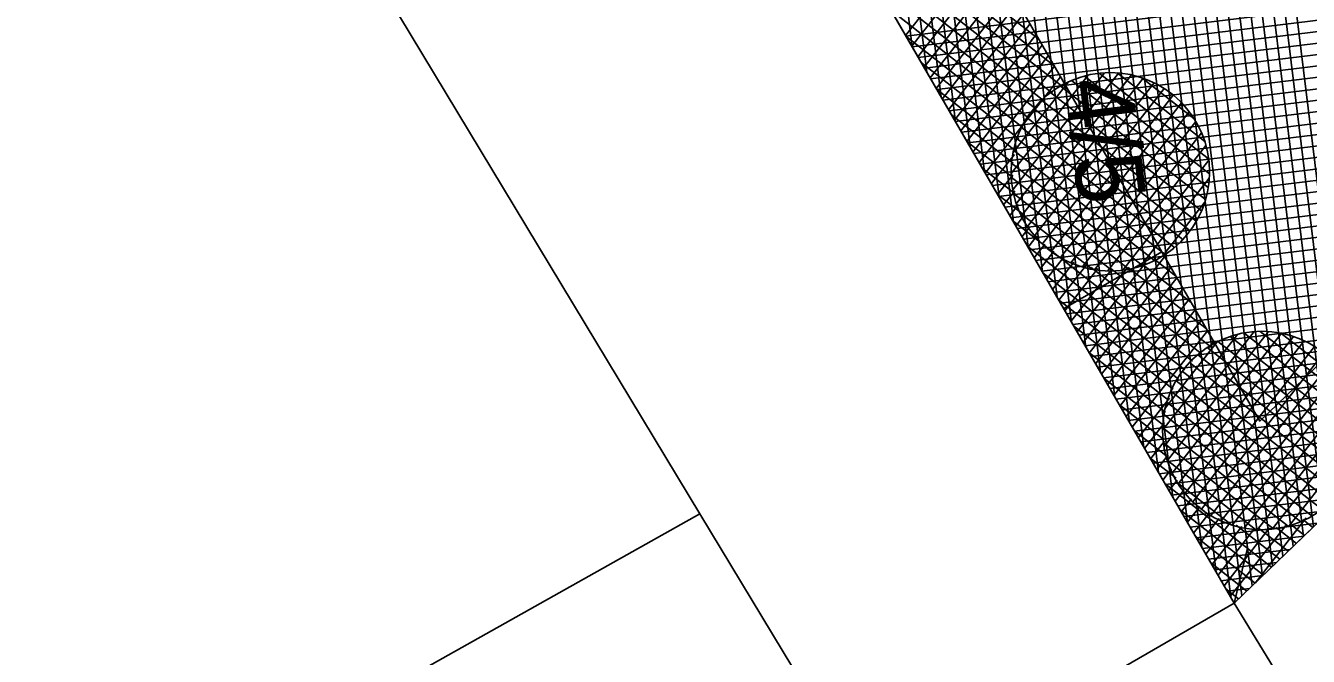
# Model space of a CAD drawing. Extents: x -566982 to -566809, y -1095912 to -1095685.
# Drawn here: x -566913.58 to -566890.96, y -1095828.46 to -1095817.35 of the extents above; entities that cross this region are included whole.
import ezdxf

# ---------------------------------------------------------------- set-up
doc = ezdxf.new("R2010")
doc.units = 0
for name, color, linetype in [('Vrstva 1', 7, 'Continuous'), ('Vrstva 26', 7, 'Continuous'), ('Vrstva 4', 7, 'Continuous'), ('Vrstva 40', 7, 'Continuous'), ('Vrstva 41', 7, 'Continuous'), ('Vrstva 42', 7, 'Continuous'), ('Vrstva 43', 7, 'Continuous'), ('Vrstva 44', 7, 'Continuous')]:
    doc.layers.add(name, color=color, linetype=linetype)

msp = doc.modelspace()

# ---------------------------------------------------------------- linework, layer by layer
at = {"layer": 'Vrstva 1'}
for p, q in [((-566956.66, -1095716.28), (-566892.27, -1095827.53)), ((-566928.71, -1095781.18), (-566901.69, -1095825.95)), ((-566880.71, -1095816.4), (-566892.27, -1095827.53)), ((-566901.69, -1095825.95), (-566898.55, -1095831.15)), ((-566898.55, -1095831.15), (-566892.27, -1095827.53)), ((-566892.27, -1095827.53), (-566889.61, -1095831.87))]:
    msp.add_line(p, q, dxfattribs=at)
at = {"layer": 'Vrstva 26'}
msp.add_line((-566892.034, -1095826.558), (-566892.27, -1095827.53), dxfattribs=at)
at = {"layer": 'Vrstva 4'}
msp.add_line((-566906.65, -1095828.74), (-566901.69, -1095825.95), dxfattribs=at)
at = {"layer": 'Vrstva 41'}
for p, q in [((-566899.133, -1095815.673), (-566895.47, -1095818.539)), ((-566898.864, -1095816.137), (-566895.629, -1095818.669)), ((-566896.416, -1095816.394), (-566897.738, -1095818.083)), ((-566898.595, -1095816.602), (-566895.766, -1095818.815)), ((-566897.348, -1095816.611), (-566898.062, -1095817.523)), ((-566897.091, -1095816.607), (-566897.954, -1095817.71)), ((-566896.793, -1095816.551), (-566897.846, -1095817.896)), ((-566897.663, -1095816.57), (-566895.292, -1095818.425)), ((-566896.301, -1095816.572), (-566897.63, -1095818.269)), ((-566897.286, -1095816.61), (-566895.446, -1095818.05)), ((-566896.983, -1095816.594), (-566895.714, -1095817.586)), ((-566896.194, -1095816.758), (-566897.522, -1095818.456)), ((-566898.327, -1095817.066), (-566895.886, -1095818.976)), ((-566896.086, -1095816.945), (-566897.414, -1095818.642)), ((-566895.978, -1095817.131), (-566897.306, -1095818.829)), ((-566895.87, -1095817.318), (-566897.198, -1095819.016)), ((-566898.058, -1095817.53), (-566895.987, -1095819.15)), ((-566895.762, -1095817.504), (-566897.09, -1095819.202)), ((-566895.654, -1095817.691), (-566896.982, -1095819.389)), ((-566897.789, -1095817.994), (-566896.068, -1095819.341)), ((-566895.546, -1095817.878), (-566896.874, -1095819.575)), ((-566895.438, -1095818.064), (-566896.766, -1095819.762)), ((-566895.33, -1095818.251), (-566896.658, -1095819.948)), ((-566897.521, -1095818.458), (-566896.129, -1095819.547)), ((-566897.252, -1095818.922), (-566896.166, -1095819.772)), ((-566896.983, -1095819.387), (-566896.168, -1095820.025)), ((-566896.144, -1095819.616), (-566896.55, -1095820.135)), ((-566896.715, -1095819.851), (-566896.129, -1095820.309)), ((-566896.171, -1095819.975), (-566896.442, -1095820.321)), ((-566896.138, -1095820.257), (-566896.334, -1095820.508)), ((-566896.446, -1095820.315), (-566896.008, -1095820.658)), ((-566896.073, -1095820.499), (-566896.226, -1095820.695)), ((-566895.982, -1095820.707), (-566896.118, -1095820.881)), ((-566896.177, -1095820.779), (-566893.003, -1095823.263)), ((-566895.872, -1095820.891), (-566896.01, -1095821.068)), ((-566895.746, -1095821.055), (-566895.902, -1095821.254)), ((-566895.605, -1095821.199), (-566895.794, -1095821.441)), ((-566895.909, -1095821.243), (-566893.136, -1095823.413)), ((-566895.449, -1095821.325), (-566895.686, -1095821.627)), ((-566893.494, -1095821.422), (-566894.823, -1095823.12)), ((-566895.28, -1095821.432), (-566895.578, -1095821.814)), ((-566895.093, -1095821.519), (-566895.47, -1095822)), ((-566894.891, -1095821.585), (-566895.362, -1095822.187)), ((-566894.671, -1095821.628), (-566895.254, -1095822.374)), ((-566894.422, -1095821.634), (-566895.146, -1095822.56)), ((-566894.153, -1095821.615), (-566895.039, -1095822.747)), ((-566893.828, -1095821.524), (-566894.931, -1095822.933)), ((-566894.791, -1095821.61), (-566892.851, -1095823.128)), ((-566893.386, -1095821.609), (-566894.715, -1095823.306)), ((-566894.435, -1095821.634), (-566892.68, -1095823.007)), ((-566894.139, -1095821.612), (-566892.759, -1095822.692)), ((-566893.893, -1095821.551), (-566893.028, -1095822.228)), ((-566893.684, -1095821.46), (-566893.297, -1095821.763)), ((-566895.64, -1095821.707), (-566893.251, -1095823.577)), ((-566893.278, -1095821.795), (-566894.607, -1095823.493)), ((-566893.17, -1095821.982), (-566894.499, -1095823.679)), ((-566895.371, -1095822.172), (-566893.347, -1095823.756)), ((-566893.062, -1095822.168), (-566894.391, -1095823.866)), ((-566892.954, -1095822.355), (-566894.283, -1095824.053)), ((-566892.846, -1095822.541), (-566894.175, -1095824.239)), ((-566895.103, -1095822.636), (-566893.424, -1095823.949)), ((-566892.738, -1095822.728), (-566894.067, -1095824.426)), ((-566892.63, -1095822.914), (-566892.728, -1095823.039)), ((-566894.834, -1095823.1), (-566893.479, -1095824.16)), ((-566894.565, -1095823.564), (-566893.506, -1095824.393)), ((-566893.41, -1095823.911), (-566893.959, -1095824.612)), ((-566894.297, -1095824.028), (-566893.501, -1095824.651)), ((-566893.505, -1095824.357), (-566893.851, -1095824.799)), ((-566894.028, -1095824.492), (-566893.444, -1095824.949)), ((-566893.499, -1095824.674), (-566893.743, -1095824.985)), ((-566893.759, -1095824.957), (-566893.291, -1095825.323)), ((-566893.449, -1095824.934), (-566893.635, -1095825.172)), ((-566893.371, -1095825.159), (-566893.527, -1095825.358)), ((-566893.491, -1095825.421), (-566891.609, -1095826.893)), ((-566893.273, -1095825.358), (-566893.419, -1095825.545)), ((-566893.155, -1095825.533), (-566893.311, -1095825.732)), ((-566893.022, -1095825.687), (-566893.203, -1095825.918)), ((-566893.222, -1095825.885), (-566891.754, -1095827.033)), ((-566892.874, -1095825.822), (-566893.095, -1095826.105)), ((-566892.712, -1095825.939), (-566892.987, -1095826.291)), ((-566892.535, -1095826.038), (-566892.879, -1095826.478)), ((-566892.343, -1095826.117), (-566892.771, -1095826.664)), ((-566892.134, -1095826.175), (-566892.663, -1095826.851)), ((-566891.36, -1095826.16), (-566892.339, -1095827.411)), ((-566892.233, -1095826.151), (-566891.463, -1095826.753)), ((-566891.002, -1095826.026), (-566891.9, -1095827.173)), ((-566891.278, -1095826.137), (-566891.027, -1095826.333)), ((-566891.058, -1095826.055), (-566890.881, -1095826.193)), ((-566892.954, -1095826.349), (-566891.9, -1095827.174)), ((-566891.905, -1095826.207), (-566892.555, -1095827.037)), ((-566891.648, -1095826.202), (-566892.447, -1095827.224)), ((-566891.839, -1095826.205), (-566891.318, -1095826.613)), ((-566891.53, -1095826.193), (-566891.172, -1095826.473)), ((-566892.685, -1095826.813), (-566892.045, -1095827.314)), ((-566892.416, -1095827.277), (-566892.191, -1095827.454))]:
    msp.add_line(p, q, dxfattribs=at)
at = {"layer": 'Vrstva 42'}
msp.add_line((-566895.276, -1095822.337), (-566893.544, -1095821.335), dxfattribs=at)
msp.add_lwpolyline([(-566834.15, -1095760.69), (-566836.072, -1095760.136), (-566841.286, -1095779.189), (-566855.268, -1095796.126), (-566881.984, -1095814.851), (-566891.818, -1095824.318), (-566954.342, -1095716.292), (-566956.66, -1095716.28), (-566892.27, -1095827.53), (-566880.71, -1095816.4), (-566853.9, -1095797.61), (-566839.47, -1095780.13)], close=True, dxfattribs=at)
at = {"layer": 'Vrstva 43'}
for p, q in [((-566901.033, -1095792.426), (-566897.945, -1095817.724)), ((-566900.777, -1095792.867), (-566897.69, -1095818.165)), ((-566900.522, -1095793.308), (-566897.435, -1095818.607)), ((-566900.267, -1095793.749), (-566897.179, -1095819.048)), ((-566900.011, -1095794.19), (-566896.924, -1095819.489)), ((-566899.756, -1095794.631), (-566896.669, -1095819.93)), ((-566899.501, -1095795.072), (-566896.414, -1095820.371)), ((-566899.245, -1095795.513), (-566896.158, -1095820.812)), ((-566898.99, -1095795.955), (-566895.903, -1095821.253)), ((-566898.735, -1095796.396), (-566895.648, -1095821.694)), ((-566898.479, -1095796.837), (-566895.392, -1095822.135)), ((-566898.224, -1095797.278), (-566895.137, -1095822.577)), ((-566897.969, -1095797.719), (-566894.882, -1095823.018)), ((-566897.714, -1095798.16), (-566894.626, -1095823.459)), ((-566897.458, -1095798.601), (-566894.371, -1095823.9)), ((-566897.203, -1095799.042), (-566894.116, -1095824.341)), ((-566896.948, -1095799.484), (-566893.86, -1095824.782)), ((-566896.692, -1095799.925), (-566893.605, -1095825.223)), ((-566896.437, -1095800.366), (-566893.35, -1095825.664)), ((-566896.182, -1095800.807), (-566893.094, -1095826.106)), ((-566895.926, -1095801.248), (-566892.839, -1095826.547)), ((-566895.671, -1095801.689), (-566892.584, -1095826.988)), ((-566895.416, -1095802.13), (-566892.328, -1095827.429)), ((-566895.16, -1095802.571), (-566892.131, -1095827.396)), ((-566894.905, -1095803.012), (-566891.951, -1095827.223)), ((-566894.65, -1095803.454), (-566891.77, -1095827.049)), ((-566894.394, -1095803.895), (-566891.59, -1095826.875)), ((-566894.139, -1095804.336), (-566891.41, -1095826.702)), ((-566893.884, -1095804.777), (-566891.23, -1095826.528)), ((-566893.629, -1095805.218), (-566891.049, -1095826.355)), ((-566893.373, -1095805.659), (-566890.869, -1095826.181)), ((-566893.118, -1095806.1), (-566890.689, -1095826.007)), ((-566892.863, -1095806.541), (-566890.508, -1095825.834)), ((-566892.607, -1095806.983), (-566890.328, -1095825.66)), ((-566892.352, -1095807.424), (-566890.148, -1095825.487)), ((-566898.056, -1095817.533), (-566879.01, -1095815.208)), ((-566897.947, -1095817.721), (-566879.358, -1095815.452)), ((-566897.838, -1095817.909), (-566879.706, -1095815.696)), ((-566897.73, -1095818.097), (-566880.054, -1095815.94)), ((-566897.621, -1095818.286), (-566880.402, -1095816.184)), ((-566897.512, -1095818.474), (-566880.738, -1095816.427)), ((-566897.403, -1095818.662), (-566880.977, -1095816.657)), ((-566897.294, -1095818.85), (-566881.217, -1095816.888)), ((-566897.185, -1095819.038), (-566881.457, -1095817.119)), ((-566897.076, -1095819.226), (-566881.696, -1095817.35)), ((-566896.967, -1095819.415), (-566881.936, -1095817.58)), ((-566896.858, -1095819.603), (-566882.176, -1095817.811)), ((-566896.749, -1095819.791), (-566882.415, -1095818.042)), ((-566896.64, -1095819.979), (-566882.655, -1095818.273)), ((-566896.531, -1095820.167), (-566882.895, -1095818.503)), ((-566896.422, -1095820.356), (-566883.134, -1095818.734)), ((-566896.314, -1095820.544), (-566883.374, -1095818.965)), ((-566896.205, -1095820.732), (-566883.613, -1095819.195)), ((-566896.096, -1095820.92), (-566883.853, -1095819.426)), ((-566895.987, -1095821.108), (-566884.093, -1095819.657)), ((-566895.878, -1095821.297), (-566884.332, -1095819.888)), ((-566895.769, -1095821.485), (-566884.572, -1095820.118)), ((-566895.66, -1095821.673), (-566884.812, -1095820.349)), ((-566895.551, -1095821.861), (-566885.051, -1095820.58)), ((-566895.442, -1095822.049), (-566885.291, -1095820.811)), ((-566895.333, -1095822.238), (-566885.531, -1095821.041)), ((-566895.224, -1095822.426), (-566885.77, -1095821.272)), ((-566895.115, -1095822.614), (-566886.01, -1095821.503)), ((-566895.006, -1095822.802), (-566886.25, -1095821.733)), ((-566894.898, -1095822.99), (-566886.489, -1095821.964)), ((-566894.789, -1095823.178), (-566886.729, -1095822.195)), ((-566894.68, -1095823.367), (-566886.968, -1095822.426)), ((-566894.571, -1095823.555), (-566887.208, -1095822.656)), ((-566894.462, -1095823.743), (-566887.448, -1095822.887)), ((-566894.353, -1095823.931), (-566887.687, -1095823.118)), ((-566894.244, -1095824.119), (-566887.927, -1095823.349)), ((-566894.135, -1095824.308), (-566888.167, -1095823.579)), ((-566894.026, -1095824.496), (-566888.406, -1095823.81)), ((-566893.917, -1095824.684), (-566888.646, -1095824.041)), ((-566893.808, -1095824.872), (-566888.886, -1095824.271)), ((-566893.699, -1095825.06), (-566889.125, -1095824.502)), ((-566893.59, -1095825.249), (-566889.365, -1095824.733)), ((-566893.482, -1095825.437), (-566889.605, -1095824.964)), ((-566893.373, -1095825.625), (-566889.844, -1095825.194)), ((-566893.264, -1095825.813), (-566890.084, -1095825.425)), ((-566893.155, -1095826.001), (-566890.323, -1095825.656)), ((-566893.046, -1095826.19), (-566890.563, -1095825.887)), ((-566892.937, -1095826.378), (-566890.803, -1095826.117)), ((-566892.828, -1095826.566), (-566891.042, -1095826.348)), ((-566892.719, -1095826.754), (-566891.282, -1095826.579)), ((-566892.61, -1095826.942), (-566891.522, -1095826.809)), ((-566892.501, -1095827.131), (-566891.761, -1095827.04)), ((-566892.392, -1095827.319), (-566892.001, -1095827.271)), ((-566892.283, -1095827.507), (-566892.241, -1095827.502))]:
    msp.add_line(p, q, dxfattribs=at)
msp.add_lwpolyline([(-566834.15, -1095760.69), (-566843.76, -1095757.92), (-566848.55, -1095775.42), (-566860.75, -1095790.2), (-566887.09, -1095808.66), (-566890.01, -1095811.47), (-566945.07, -1095716.34), (-566956.66, -1095716.28), (-566892.27, -1095827.53), (-566880.71, -1095816.4), (-566853.9, -1095797.61), (-566839.47, -1095780.13)], close=True, dxfattribs=at)
at = {"layer": 'Vrstva 44'}
for p, q in [((-566894.844, -1095818.22), (-566896.202, -1095819.955)), ((-566894.557, -1095818.178), (-566896.172, -1095820.242)), ((-566894.306, -1095818.182), (-566896.11, -1095820.487)), ((-566894.078, -1095818.215), (-566896.021, -1095820.698)), ((-566894.91, -1095818.235), (-566892.706, -1095819.96)), ((-566894.647, -1095818.186), (-566892.719, -1095819.695)), ((-566894.331, -1095818.18), (-566892.788, -1095819.388)), ((-566895.191, -1095818.339), (-566896.169, -1095819.589)), ((-566893.872, -1095818.275), (-566895.914, -1095820.885)), ((-566893.68, -1095818.356), (-566895.79, -1095821.052)), ((-566893.504, -1095818.455), (-566895.651, -1095821.199)), ((-566895.332, -1095818.413), (-566892.775, -1095820.414)), ((-566895.134, -1095818.314), (-566892.725, -1095820.198)), ((-566893.896, -1095818.267), (-566892.98, -1095818.983)), ((-566895.663, -1095818.661), (-566892.937, -1095820.794)), ((-566895.508, -1095818.528), (-566892.846, -1095820.612)), ((-566893.342, -1095818.572), (-566895.497, -1095821.326)), ((-566893.195, -1095818.709), (-566895.329, -1095821.437)), ((-566895.799, -1095818.809), (-566893.046, -1095820.963)), ((-566893.063, -1095818.865), (-566895.147, -1095821.529)), ((-566896.019, -1095819.145), (-566893.321, -1095821.256)), ((-566895.918, -1095818.97), (-566893.174, -1095821.117)), ((-566892.945, -1095819.039), (-566894.951, -1095821.602)), ((-566896.101, -1095819.335), (-566893.486, -1095821.38)), ((-566892.845, -1095819.235), (-566894.734, -1095821.649)), ((-566896.16, -1095819.543), (-566893.672, -1095821.489)), ((-566892.768, -1095819.461), (-566894.499, -1095821.673)), ((-566896.195, -1095819.769), (-566893.884, -1095821.577)), ((-566892.716, -1095819.719), (-566894.233, -1095821.658)), ((-566896.2, -1095820.019), (-566894.126, -1095821.642)), ((-566892.707, -1095820.033), (-566893.926, -1095821.59)), ((-566896.161, -1095820.304), (-566894.413, -1095821.671)), ((-566892.791, -1095820.464), (-566893.531, -1095821.41)), ((-566896.047, -1095820.647), (-566894.774, -1095821.642)), ((-566891.918, -1095822.739), (-566893.506, -1095824.769)), ((-566891.665, -1095822.74), (-566893.447, -1095825.017)), ((-566891.434, -1095822.769), (-566893.361, -1095825.233)), ((-566892.099, -1095822.763), (-566890.036, -1095824.378)), ((-566891.81, -1095822.736), (-566890.076, -1095824.093)), ((-566891.446, -1095822.767), (-566890.197, -1095823.744)), ((-566892.211, -1095822.789), (-566893.529, -1095824.473)), ((-566892.569, -1095822.921), (-566893.486, -1095824.093)), ((-566891.225, -1095822.826), (-566893.256, -1095825.422)), ((-566891.032, -1095822.905), (-566893.134, -1095825.591)), ((-566890.854, -1095823.002), (-566892.998, -1095825.741)), ((-566892.555, -1095822.915), (-566890.073, -1095824.857)), ((-566892.342, -1095822.828), (-566890.038, -1095824.63)), ((-566892.907, -1095823.147), (-566890.212, -1095825.257)), ((-566890.69, -1095823.117), (-566892.846, -1095825.872)), ((-566892.742, -1095823.023), (-566890.132, -1095825.065)), ((-566893.184, -1095823.439), (-566890.43, -1095825.593)), ((-566893.055, -1095823.286), (-566890.312, -1095825.432)), ((-566890.541, -1095823.25), (-566892.679, -1095825.984)), ((-566890.407, -1095823.404), (-566892.499, -1095826.078)), ((-566893.294, -1095823.606), (-566890.566, -1095825.741)), ((-566890.287, -1095823.576), (-566892.304, -1095826.153)), ((-566893.385, -1095823.789), (-566890.72, -1095825.874)), ((-566890.185, -1095823.769), (-566892.09, -1095826.204)), ((-566893.457, -1095823.987), (-566890.895, -1095825.992)), ((-566890.104, -1095823.991), (-566891.857, -1095826.231)), ((-566893.507, -1095824.201), (-566891.093, -1095826.091)), ((-566890.049, -1095824.245), (-566891.596, -1095826.222)), ((-566893.529, -1095824.438), (-566891.316, -1095826.17)), ((-566890.034, -1095824.551), (-566891.297, -1095826.164)), ((-566893.517, -1095824.702), (-566891.577, -1095826.22)), ((-566893.449, -1095825.009), (-566891.89, -1095826.229)), ((-566893.267, -1095825.405), (-566892.318, -1095826.148))]:
    msp.add_line(p, q, dxfattribs=at)
for centre in [(-566894.453, -1095819.924), (-566891.781, -1095824.484)]:
    msp.add_circle(centre, 1.75, dxfattribs=at)

# ---------------------------------------------------------------- texts
at = {"layer": 'Vrstva 40'}
msp.add_text('4/5', height=1.2, rotation=276.9575, dxfattribs=at).set_placement((-566895.272, -1095818.331))

doc.saveas('drawing.dxf')
